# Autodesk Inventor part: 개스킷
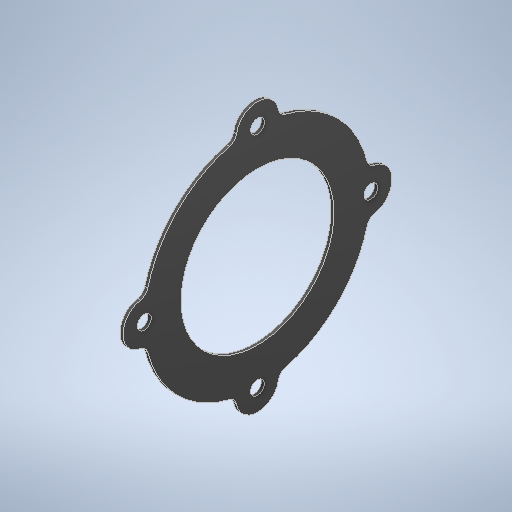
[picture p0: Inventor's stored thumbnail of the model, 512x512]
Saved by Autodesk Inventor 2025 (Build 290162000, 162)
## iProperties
Created: 2024-08
Part Number: 개스킷
Material: 황동, 연질 노란색
Document SubType Name: Modeling
Designer: 학생
Density: 8.47 g/cm^3
Appearance: 기본값
Author: jhkim
Sending System: Autodesk Inventor 2025
Preprocessor: ST-DEVELOPER v20
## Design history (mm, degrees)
feature "솔리드2"
node "솔리드1"
